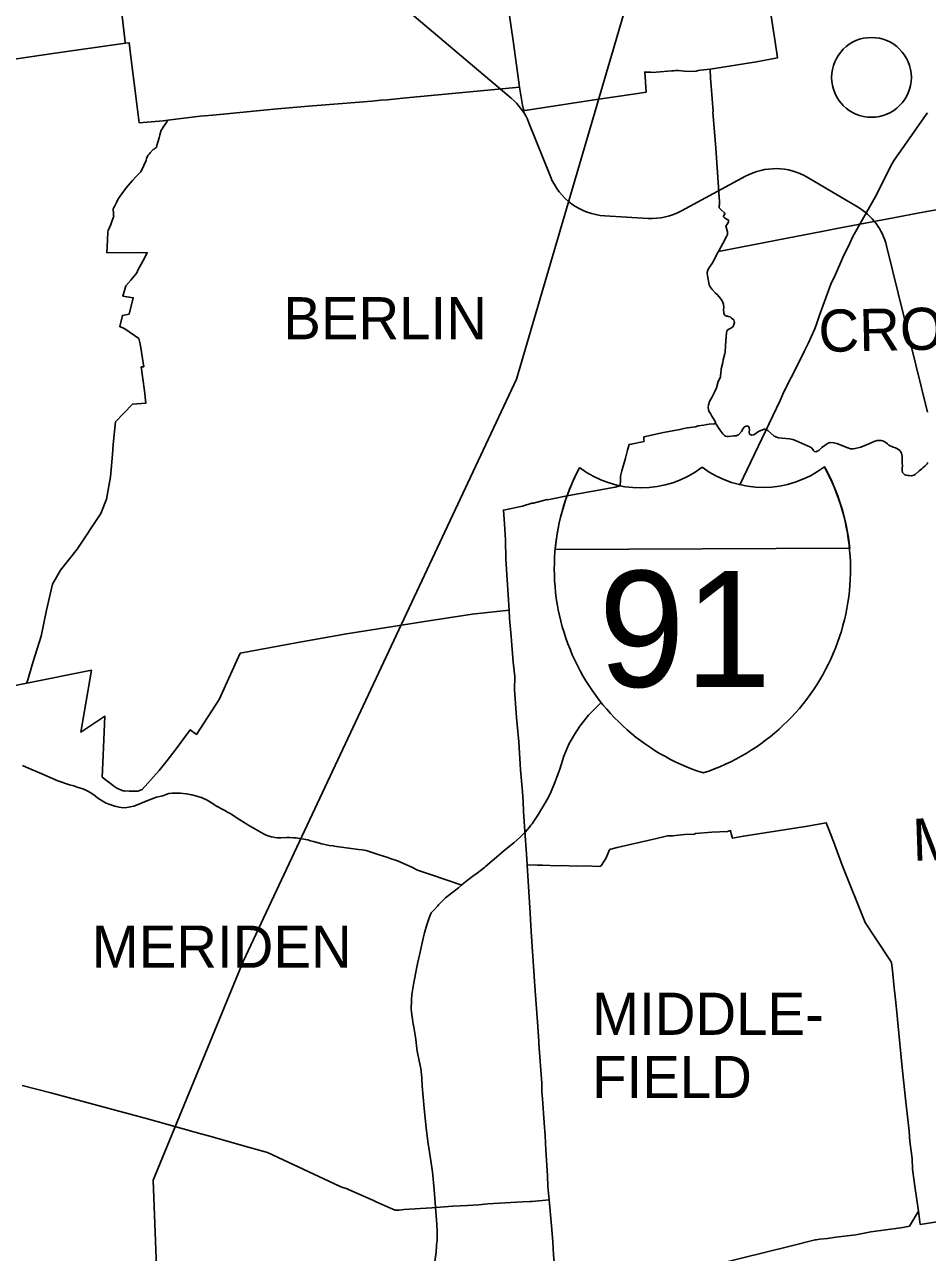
# Model space of a CAD drawing. Extents: x 0 to 2603, y -226 to 830.
# Drawn here: x 176.05 to 204.97, y 575 to 614.31 of the extents above; entities that cross this region are included whole.
import ezdxf

# ---------------------------------------------------------------- set-up
doc = ezdxf.new("R2010")
doc.units = 0
for name, color, linetype in [('CT_TSH_Map_Cities_Text', 7, 'Continuous'), ('CT_TSH_Map_Districts', 7, 'Continuous'), ('CT_TSH_Map_Interstate_Roads', 7, 'Continuous'), ('CT_TSH_Map_Town_Limits', 7, 'Continuous'), ('CT_TSH_Map_Town_Text', 7, 'Continuous'), ('CT_TSH_Map_US_and_State_Routes', 7, 'Continuous')]:
    doc.layers.add(name, color=color, linetype=linetype)

msp = doc.modelspace()

# ---------------------------------------------------------------- linework, layer by layer
at = {"layer": 'CT_TSH_Map_Cities_Text'}
msp.add_circle((203.175, 612.614), 1.277, dxfattribs=at)
at = {"layer": 'CT_TSH_Map_Districts'}
for points in [[(175.981, 580.345), (176.896, 580.103), (179.99, 579.274), (181.738, 578.781), (181.988, 578.714), (183.069, 578.41), (183.834, 578.191), (186.141, 577.117), (186.22, 577.089), (186.388, 577.037), (186.455, 577.002), (187.133, 576.7), (187.211, 576.671), (187.337, 576.606), (187.776, 576.414), (187.925, 576.344), (187.984, 576.349), (188.052, 576.351), (188.202, 576.366), (189.098, 576.427), (189.771, 576.472), (190.237, 576.502), (190.604, 576.525), (190.89, 576.547), (192.005, 576.618), (192.236, 576.624), (192.315, 576.628), (192.851, 576.685)], [(192.851, 576.685), (192.932, 575.851), (192.974, 575.341), (192.998, 574.92), (193.038, 574.456), (193.141, 573.228), (193.934, 573.484), (194.783, 573.725)]]:
    msp.add_lwpolyline(points, dxfattribs=at)
at = {"layer": 'CT_TSH_Map_Interstate_Roads'}
for p, q in [((202.478, 597.543), (193.046, 597.503)), ((190.056, 586.762), (189.948, 586.669)), ((189.454, 586.26), (189.4, 586.205)), ((189.636, 586.423), (189.538, 586.345))]:
    msp.add_line(p, q, dxfattribs=at)
for points in [[(204.929, 611.423), (204.234, 610.438), (203.998, 610.107)], [(204.97, 611.479), (204.929, 611.423)], [(203.998, 610.107), (203.897, 609.962), (203.809, 609.809), (203.642, 609.476), (203.299, 608.784)], [(203.15, 608.536), (202.584, 607.521)], [(203.299, 608.784), (203.15, 608.536)], [(202.584, 607.521), (202.481, 607.31)], [(202.481, 607.31), (202.254, 606.848)], [(202.254, 606.848), (202.022, 606.308)], [(202.022, 606.308), (201.87, 605.994), (201.513, 604.999)], [(201.513, 604.999), (201.408, 604.679)], [(201.408, 604.679), (201.346, 604.542), (201.158, 604.113)], [(201.158, 604.113), (201.036, 603.856), (200.842, 603.462)], [(200.842, 603.462), (200.374, 602.548)], [(200.287, 602.346), (200.249, 602.274), (198.957, 599.575)], [(200.374, 602.548), (200.287, 602.346)], [(194.518, 592.601), (194.113, 592.196), (193.837, 591.841), (193.665, 591.58), (193.486, 591.263), (193.325, 590.884), (193.194, 590.471), (193.041, 590.041), (192.901, 589.694), (192.791, 589.498), (192.51, 589.025), (192.344, 588.774)], [(175.987, 590.587), (176.109, 590.529), (176.611, 590.315), (177.12, 590.094), (177.489, 589.969), (177.628, 589.929), (177.745, 589.895), (177.916, 589.84), (177.998, 589.803), (178.105, 589.75)], [(178.105, 589.75), (178.206, 589.687), (178.311, 589.609)], [(178.311, 589.609), (178.401, 589.536), (178.503, 589.473), (178.589, 589.424), (178.67, 589.383), (178.789, 589.335), (178.943, 589.28), (179.084, 589.247), (179.214, 589.234), (179.333, 589.239), (179.442, 589.257), (179.55, 589.288), (179.696, 589.339), (179.969, 589.45), (180.276, 589.569), (180.487, 589.617), (180.586, 589.658), (180.671, 589.683), (180.777, 589.7), (180.9, 589.703), (180.98, 589.697)], [(180.98, 589.697), (181.052, 589.7), (181.232, 589.681), (181.416, 589.649), (181.576, 589.606), (181.742, 589.545), (181.907, 589.47), (182.094, 589.358), (182.217, 589.277)], [(182.217, 589.277), (182.243, 589.267), (182.315, 589.218), (182.486, 589.128)], [(182.486, 589.128), (182.534, 589.1)], [(182.534, 589.1), (182.551, 589.09)], [(182.551, 589.09), (182.658, 589.034), (182.863, 588.9), (183.17, 588.702), (183.234, 588.665), (183.329, 588.612), (183.649, 588.426), (183.727, 588.385), (183.792, 588.356)], [(192.28, 588.685), (192.271, 588.67), (192.227, 588.606), (192.087, 588.446), (192.035, 588.395), (191.937, 588.3), (191.832, 588.205), (191.722, 588.11)], [(192.344, 588.774), (192.306, 588.716), (192.28, 588.685)], [(183.792, 588.356), (183.891, 588.319)], [(183.891, 588.319), (183.949, 588.304)], [(183.949, 588.304), (184.022, 588.288)], [(184.022, 588.288), (184.067, 588.28), (184.152, 588.271)], [(184.152, 588.271), (184.258, 588.267), (184.43, 588.277), (184.555, 588.276)], [(184.555, 588.276), (184.666, 588.272), (184.755, 588.264)], [(184.755, 588.264), (184.864, 588.251), (184.997, 588.228)], [(184.997, 588.228), (185.056, 588.217), (185.13, 588.2), (185.217, 588.177)], [(185.217, 588.177), (185.307, 588.149)], [(185.307, 588.149), (185.573, 588.078)], [(185.573, 588.078), (185.671, 588.054), (185.814, 588.028), (185.958, 588.009), (185.964, 588.006)], [(191.722, 588.11), (191.41, 587.859), (191.241, 587.719), (190.812, 587.349)], [(185.964, 588.006), (186.043, 587.996)], [(186.043, 587.996), (186.746, 587.9), (186.868, 587.887)], [(186.868, 587.887), (186.99, 587.861), (187.415, 587.729)], [(187.415, 587.729), (187.691, 587.637)], [(187.691, 587.637), (187.797, 587.601)], [(187.797, 587.601), (188.002, 587.53)], [(188.002, 587.53), (188.453, 587.329), (188.641, 587.234)], [(190.812, 587.349), (190.78, 587.322), (190.544, 587.139)], [(188.641, 587.234), (188.701, 587.215)], [(188.701, 587.215), (188.863, 587.163)], [(188.863, 587.163), (189.053, 587.092)], [(189.053, 587.092), (190.061, 586.758)], [(190.544, 587.139), (190.406, 587.041), (190.13, 586.828), (190.056, 586.762)], [(189.948, 586.669), (189.731, 586.498), (189.636, 586.423)], [(189.4, 586.205), (189.314, 586.126), (189.284, 586.097), (189.179, 585.976), (189.076, 585.866)], [(189.538, 586.345), (189.485, 586.293), (189.454, 586.26)], [(189.076, 585.866), (189.012, 585.705), (188.934, 585.487)], [(188.934, 585.487), (188.859, 585.223), (188.833, 585.096), (188.71, 584.567)], [(188.71, 584.567), (188.639, 584.242), (188.639, 584.213)], [(188.639, 584.213), (188.628, 584.193), (188.514, 583.572), (188.48, 583.384), (188.453, 583.251)], [(188.453, 583.251), (188.443, 583.084), (188.44, 582.776)], [(188.44, 582.776), (188.487, 582.381), (188.504, 582.296)], [(188.504, 582.296), (188.508, 582.277), (188.562, 581.953), (188.58, 581.81), (188.612, 581.52), (188.628, 581.442), (188.694, 581.126)], [(188.694, 581.126), (188.74, 580.885), (188.765, 580.689), (188.774, 580.572)], [(188.774, 580.572), (188.788, 580.33), (188.847, 579.608), (188.912, 578.985), (188.968, 578.548), (189.073, 577.867), (189.121, 577.57), (189.141, 577.351), (189.167, 577.002)], [(189.167, 577.002), (189.253, 575.895), (189.263, 575.675), (189.263, 575.381), (189.25, 575.254)], [(189.25, 575.254), (189.251, 575.203), (189.234, 575.008), (189.203, 574.777), (189.167, 574.582)]]:
    msp.add_lwpolyline(points, dxfattribs=at)
for centre, radius, start, end in [((199.883, 596.883), 6.864, 151.8748, 252.2637), ((199.891, 596.879), 6.874, 151.8748, 174.7861), ((195.784, 602.735), 3.265, 233.2263, 307.1377), ((199.701, 602.753), 3.264, 233.3979, 307.1378), ((195.639, 596.863), 6.864, 288.272, 28.6609), ((195.648, 596.859), 6.864, 5.7168, 28.6609)]:
    msp.add_arc(centre, radius, start, end, dxfattribs=at)
at = {"layer": 'CT_TSH_Map_Town_Limits'}
for points in [[(189.831, 627.714), (189.99, 626.455), (189.992, 626.415), (190.185, 624.868), (190.333, 623.65), (190.362, 623.427), (190.457, 622.607), (190.505, 622.206), (190.545, 621.929), (190.615, 621.34), (190.942, 619.017), (191.634, 614.221), (191.7, 613.786), (191.882, 612.461), (191.909, 612.304)], [(180.424, 621.18), (179.876, 620.569), (179.763, 620.436), (179.728, 620.4), (179.654, 620.054), (179.524, 619.4), (179.344, 618.572), (179.326, 618.44), (179.132, 617.583), (179.109, 617.464), (178.992, 616.93), (178.967, 616.793), (178.941, 616.66), (178.976, 616.394), (178.999, 616.16), (179.274, 613.746), (179.284, 613.705)], [(199.635, 616.718), (200.09, 613.749), (200.165, 613.239), (199.493, 613.117), (198.006, 612.874)], [(179.284, 613.705), (176.961, 613.377), (175.514, 613.165), (174.487, 613.017), (173.131, 612.814), (172.797, 612.77), (172.264, 612.695), (171.909, 612.641), (171.804, 612.634), (171.526, 612.593), (171.331, 612.57), (171.193, 612.548), (171.035, 612.53), (170.801, 612.497), (170.707, 612.494), (170.377, 612.444), (170.012, 612.376), (169.316, 612.288), (168.967, 612.257), (168.626, 612.205), (168.492, 612.2)], [(179.284, 613.705), (179.405, 613.721), (179.447, 613.353), (179.57, 612.431), (179.674, 611.585), (179.712, 611.243), (179.729, 611.155), (180.49, 611.224), (180.638, 611.241)], [(198.006, 612.874), (197.704, 612.844), (197.628, 612.832), (197.565, 612.814), (197.358, 612.805), (197.185, 612.811), (196.992, 612.831), (196.899, 612.829), (196.844, 612.824), (196.787, 612.823), (196.281, 612.776), (196.191, 612.773), (196.114, 612.783), (195.941, 612.785), (195.913, 612.79), (195.958, 612.144), (195.614, 612.092), (194.365, 611.903), (192.074, 611.55), (192.038, 611.54), (192.005, 611.726), (191.909, 612.304)], [(198.272, 607.038), (198.414, 607.292), (198.534, 607.52), (198.561, 607.582), (198.565, 607.672), (198.521, 607.817), (198.516, 607.847), (198.53, 607.881), (198.593, 607.979), (198.602, 608.023), (198.594, 608.048), (198.572, 608.057), (198.468, 608.122), (198.438, 608.149), (198.441, 608.175), (198.479, 608.248), (198.465, 608.277), (198.378, 608.365), (198.331, 608.402), (198.3, 608.434), (198.298, 608.503), (198.306, 608.532), (198.307, 608.627), (198.188, 610.347), (198.1, 611.51), (198.102, 611.522), (198.044, 612.33), (198.026, 612.578), (198.006, 612.874)], [(191.909, 612.304), (188.164, 611.95), (187.678, 611.9), (187.463, 611.885), (187.173, 611.855), (186.508, 611.798), (186.236, 611.779), (185.276, 611.705), (184.647, 611.649), (184.033, 611.601), (183.93, 611.587), (182.079, 611.408), (181.683, 611.375), (180.638, 611.241)], [(180.638, 611.241), (180.591, 611.158), (180.495, 611.021), (180.452, 610.949), (180.434, 610.927), (180.389, 610.774), (180.368, 610.681), (180.291, 610.436), (180.276, 610.372), (180.25, 610.357), (180.206, 610.319), (180.174, 610.301), (180.08, 610.196), (180.045, 610.161), (180.004, 610.11), (179.964, 610.013), (179.944, 609.95), (179.87, 609.788), (179.817, 609.678), (179.804, 609.644), (179.775, 609.595), (179.64, 609.449), (179.515, 609.312), (179.305, 609.08), (179.175, 608.89), (179.162, 608.874), (179.046, 608.701), (179.007, 608.634), (178.93, 608.483), (178.906, 608.428), (178.895, 608.407), (178.891, 608.389), (178.905, 608.271), (178.908, 608.196), (178.911, 608.173), (178.863, 608.031), (178.816, 607.904), (178.733, 607.711), (178.723, 607.672), (178.708, 607.406), (178.695, 607), (179.699, 607.004), (179.986, 606.998), (179.844, 606.725), (179.683, 606.44), (179.648, 606.361), (179.463, 606.121), (179.299, 605.945), (179.203, 605.613), (179.535, 605.56), (179.4, 605.036), (179.188, 604.996), (179.103, 604.635), (179.264, 604.559), (179.714, 604.258), (179.757, 604.088), (179.872, 603.35), (179.79, 603.344), (179.896, 602.574), (179.935, 602.183), (179.511, 602.153), (178.968, 601.584), (178.89, 600.864), (178.867, 600.545), (178.811, 599.829), (178.677, 599.113), (178.5, 598.65), (177.744, 597.514), (177.21, 596.843), (176.952, 596.391), (176.763, 595.555), (176.582, 594.726), (176.33, 593.917), (176.123, 593.224)], [(213.423, 609.978), (213.297, 609.949), (211.955, 609.685), (211.36, 609.572), (210.76, 609.453), (210.205, 609.348), (209.692, 609.243), (208.832, 609.076), (208.469, 609.004), (208.446, 608.993), (208.174, 608.951), (206.69, 608.66), (206.258, 608.572), (205.711, 608.47), (205.252, 608.376), (204.946, 608.324), (204.548, 608.245), (204.102, 608.164), (202.012, 607.761), (201.589, 607.676), (200.476, 607.465), (198.272, 607.038)], [(198.272, 607.038), (198.237, 606.979), (198.101, 606.711), (197.943, 606.479), (197.935, 606.437), (197.918, 606.37), (197.917, 606.34), (197.923, 606.272), (197.981, 605.977), (198.006, 605.913), (198.073, 605.819), (198.178, 605.711), (198.24, 605.654), (198.343, 605.536), (198.39, 605.461), (198.432, 605.353), (198.443, 605.247), (198.441, 605.181), (198.447, 605.063), (198.467, 605.014), (198.493, 604.993), (198.532, 604.972), (198.57, 604.969), (198.602, 604.962), (198.646, 604.944), (198.698, 604.909), (198.765, 604.849), (198.783, 604.814), (198.785, 604.771), (198.78, 604.739), (198.747, 604.643), (198.692, 604.598), (198.61, 604.552), (198.582, 604.541), (198.546, 604.494), (198.532, 604.451), (198.517, 604.17), (198.5, 604.033), (198.489, 603.82), (198.481, 603.775), (198.427, 603.569), (198.414, 603.49), (198.358, 603.283), (198.359, 603.235), (198.342, 603.069), (198.336, 603.021), (198.264, 602.878), (198.21, 602.674), (198.161, 602.555), (198.075, 602.392), (198.027, 602.317), (197.989, 602.242), (197.957, 602.13), (197.943, 602.041), (197.971, 601.928), (198.02, 601.855), (198.068, 601.765), (198.124, 601.673), (198.176, 601.578), (198.184, 601.547)], [(198.184, 601.547), (198.148, 601.523), (197.983, 601.51), (197.899, 601.498), (197.804, 601.478), (197.625, 601.454), (197.543, 601.432), (197.281, 601.396), (197.171, 601.37), (197.041, 601.338), (196.517, 601.241), (195.882, 601.105), (195.887, 601.022), (195.896, 600.959), (195.481, 600.87), (195.414, 600.864), (195.358, 600.678), (195.297, 600.428), (195.177, 600.015), (195.149, 599.887), (195.142, 599.833), (195.143, 599.766), (195.136, 599.666), (195.127, 599.596), (195.129, 599.539), (194.971, 599.494), (194.196, 599.356), (193.485, 599.229), (192.912, 599.116), (192.809, 599.094), (192.787, 599.103), (192.357, 598.988), (192.296, 598.98), (192.005, 598.886), (191.391, 598.761), (191.42, 598.323), (191.456, 597.808), (191.467, 597.195), (191.545, 596.051), (191.573, 595.558)], [(198.184, 601.547), (198.315, 601.332), (198.412, 601.205), (198.466, 601.145), (198.501, 601.126), (198.547, 601.114), (198.599, 601.114), (198.776, 601.138), (198.839, 601.142), (198.886, 601.165), (198.914, 601.173), (198.931, 601.185), (199.013, 601.275), (199.068, 601.37), (199.1, 601.411), (199.126, 601.435), (199.19, 601.455), (199.212, 601.449), (199.251, 601.422), (199.263, 601.39), (199.269, 601.337), (199.26, 601.258), (199.272, 601.2), (199.285, 601.185), (199.318, 601.172), (199.343, 601.157), (199.408, 601.173), (199.56, 601.275), (199.738, 601.347), (199.765, 601.348), (199.792, 601.34), (199.855, 601.306), (200.061, 601.131), (200.15, 601.092), (200.196, 601.076), (200.554, 601.047), (200.652, 601.024), (200.743, 600.99), (201.226, 600.773), (201.25, 600.755), (201.332, 600.657), (201.355, 600.635), (201.391, 600.631), (201.436, 600.646), (201.486, 600.67), (201.589, 600.762), (201.664, 600.821), (201.794, 600.909), (201.851, 600.93), (201.972, 600.916), (202.064, 600.891), (202.419, 600.753), (202.502, 600.726), (202.594, 600.72), (202.657, 600.73), (202.836, 600.781), (203.092, 600.88), (203.286, 600.966), (203.363, 600.987), (203.413, 600.992), (203.488, 600.984), (203.558, 600.964), (203.6, 600.943), (203.645, 600.915), (203.684, 600.878), (203.734, 600.84), (203.869, 600.779), (203.95, 600.75), (204.007, 600.722), (204.08, 600.669), (204.132, 600.586), (204.159, 600.484), (204.163, 600.431), (204.158, 600.36), (204.157, 600.252), (204.166, 600.19), (204.157, 600.093), (204.161, 600.021), (204.171, 599.964), (204.199, 599.931), (204.243, 599.893), (204.274, 599.879), (204.341, 599.873), (204.387, 599.864), (204.461, 599.861), (204.528, 599.875), (204.577, 599.901), (204.7, 600.013), (204.785, 600.079), (204.835, 600.128), (204.883, 600.164), (204.954, 600.237), (204.981, 600.286)], [(191.573, 595.558), (190.386, 595.434), (188.797, 595.186), (186.363, 594.805), (184.805, 594.519), (182.961, 594.176), (182.288, 592.7), (181.556, 591.582), (181.362, 591.728), (180.907, 591.118), (180.625, 590.748), (180.363, 590.423), (179.824, 589.816), (179.679, 589.767), (179.542, 589.76), (179.403, 589.762), (179.263, 589.77), (179.233, 589.768), (179.008, 589.861), (178.944, 589.899), (178.537, 590.212), (178.561, 590.669), (178.592, 591.421), (178.629, 592.16), (177.853, 591.656), (178.2, 593.635), (176.123, 593.224)], [(191.573, 595.558), (191.588, 595.294), (191.639, 594.714), (191.7, 593.889), (191.75, 593.436), (191.746, 593.01), (191.812, 592.12), (191.878, 591.338), (191.937, 590.448), (192.005, 589.738), (192.022, 589.42), (192.029, 589.114), (192.079, 588.484), (192.126, 587.752), (192.145, 587.406)], [(176.123, 593.224), (175.643, 593.125), (175.148, 593.024), (174.694, 592.913), (174.57, 592.88), (174.686, 592.468), (174.906, 591.668), (175.006, 590.319), (175.018, 589.941), (175.02, 589.908), (175.058, 589.599), (175.075, 589.366), (175.101, 589.114), (175.261, 587.637), (174.606, 587.765), (174.108, 587.868), (173.744, 587.935)], [(192.145, 587.406), (192.485, 587.39), (192.643, 587.398), (193.137, 587.376), (193.25, 587.386), (193.734, 587.362), (194.024, 587.37), (194.441, 587.35), (194.506, 587.362), (194.648, 587.57), (194.682, 587.631), (194.784, 587.887), (194.788, 587.893), (195.029, 587.959), (195.546, 588.079), (196.25, 588.239), (196.643, 588.33), (196.801, 588.335), (197.192, 588.373), (197.509, 588.391), (197.543, 588.404), (198.065, 588.45), (198.567, 588.475), (198.666, 588.499), (198.684, 588.393), (198.721, 588.262), (199.077, 588.325), (201.126, 588.647), (201.73, 588.752), (201.786, 588.59), (201.957, 588.149), (202.237, 587.391), (202.974, 585.563), (203.308, 585.061), (203.801, 584.296), (203.819, 584.262), (203.851, 584.025), (203.906, 583.469), (203.943, 583.098), (203.999, 582.586), (204.007, 582.452), (204.173, 580.812), (204.276, 579.822), (204.384, 578.874), (204.405, 578.55), (204.476, 578.004), (204.494, 577.663), (204.568, 577.12), (204.682, 576.321)], [(192.145, 587.406), (192.245, 585.854), (192.281, 585.274), (192.396, 583.522), (192.493, 582.231), (192.523, 581.748), (192.523, 581.674), (192.615, 580.41), (192.624, 580.151), (192.641, 579.909), (192.697, 579.14), (192.723, 578.737), (192.749, 578.269), (192.796, 577.458), (192.814, 577.112), (192.851, 576.685)], [(175.981, 580.345), (176.896, 580.103), (179.99, 579.274), (181.738, 578.781), (181.988, 578.714), (183.069, 578.41), (183.834, 578.191), (186.141, 577.117), (186.22, 577.089), (186.388, 577.037), (186.455, 577.002), (187.133, 576.7), (187.211, 576.671), (187.337, 576.606), (187.776, 576.414), (187.925, 576.344), (187.984, 576.349), (188.052, 576.351), (188.202, 576.366), (189.098, 576.427), (189.771, 576.472), (190.237, 576.502), (190.604, 576.525), (190.89, 576.547), (192.005, 576.618), (192.236, 576.624), (192.315, 576.628), (192.851, 576.685)], [(204.682, 576.321), (204.736, 575.893), (205.739, 576.053), (206.59, 576.197), (206.769, 576.223), (207.67, 576.371), (207.856, 576.4), (208.645, 576.517), (209.097, 576.58), (209.647, 576.675), (209.831, 576.704), (210.142, 576.753), (210.35, 576.78), (210.599, 576.823), (210.76, 576.842), (211.346, 576.94), (211.598, 576.975), (212.188, 577.067), (212.436, 577.103)], [(192.851, 576.685), (192.932, 575.851), (192.974, 575.341), (192.998, 574.92), (193.038, 574.456), (193.141, 573.228), (193.934, 573.484), (194.783, 573.725)], [(194.783, 573.725), (195.239, 573.867), (196.787, 574.266), (197.08, 574.342), (198.457, 574.678), (198.972, 574.803), (200.568, 575.196), (201.372, 575.395), (201.402, 575.399), (201.52, 575.42), (201.769, 575.446), (202.038, 575.482), (202.678, 575.562), (203.154, 575.653), (203.956, 575.759), (204.177, 575.791), (204.396, 575.838), (204.682, 576.321)]]:
    msp.add_lwpolyline(points, dxfattribs=at)
at = {"layer": 'CT_TSH_Map_US_and_State_Routes'}
for p, q in [((191.641, 611.948), (188.316, 614.758)), ((192.895, 609.438), (192.208, 611.162)), ((199.146, 609.451), (197.095, 608.338)), ((202.73, 608.467), (201.113, 609.417)), ((196.022, 608.1), (194.633, 608.183)), ((204.968, 601.899), (203.659, 607.22))]:
    msp.add_line(p, q, dxfattribs=at)
for points in [[(200.512, 625.538), (195.77, 616.455), (191.811, 602.957), (183.058, 584.314), (180.169, 577.311)], [(164.946, 534.505), (166.172, 539.356), (166.653, 541.86), (169.173, 545.726), (172.168, 553.089), (180.318, 573.415), (180.169, 577.311)]]:
    msp.add_lwpolyline(points, dxfattribs=at)
for centre, start, end in [((190.35, 610.42), 21.7579, 49.7955), ((200.1, 607.693), 59.5702, 118.4633), ((194.753, 610.18), 201.7579, 266.5697), ((196.141, 610.097), 266.5697, 298.4633), ((201.717, 606.742), 13.8184, 59.5702)]:
    msp.add_arc(centre, 2, start, end, dxfattribs=at)

# ---------------------------------------------------------------- texts
at = {"layer": 'CT_TSH_Map_Interstate_Roads'}
msp.add_text('91', height=3.7137, dxfattribs=at).set_placement((194.437, 593.102))
at = {"layer": 'CT_TSH_Map_Town_Text'}
for s, p in [('BERLIN', (184.34, 604.228)), ('MERIDEN', (178.205, 584.11)), ('MIDDLE-', (194.23, 581.962)), ('FIELD', (194.23, 579.937))]:
    msp.add_text(s, height=1.35, dxfattribs=at).set_placement(p)
for s, rotation, p in [('CROMWELL', 1.1993, (201.492, 603.82)), ('MIDDLETOWN', 1.8898, (204.507, 587.529))]:
    msp.add_text(s, height=1.35, rotation=rotation, dxfattribs=at).set_placement(p)

doc.saveas('drawing.dxf')
